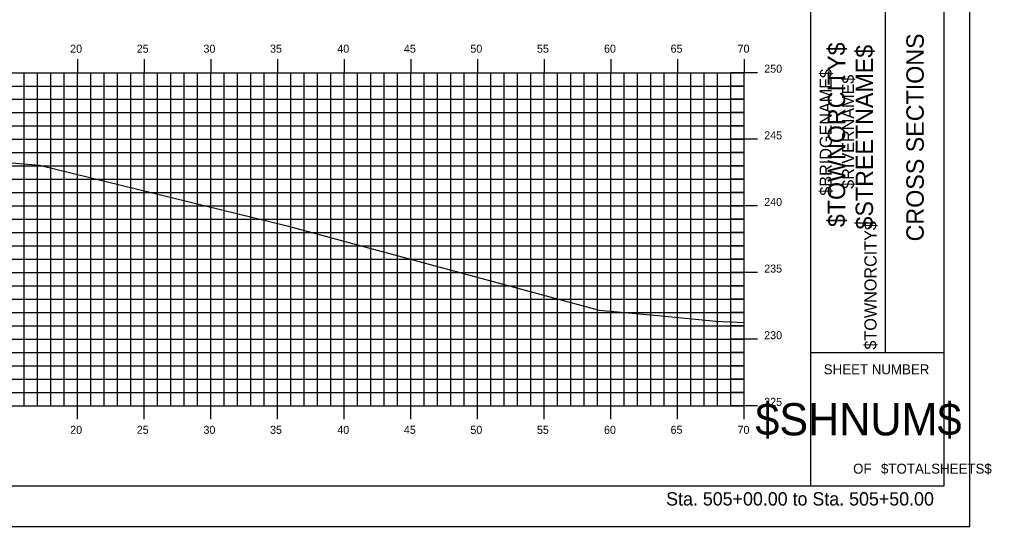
# Model space of a CAD drawing. Extents: x 1168600 to 1177589, y 610178 to 611246.
# Drawn here: x 1171529.1 to 1171602, y 610268.7 to 610306.8 of the extents above; entities that cross this region are included whole.
import ezdxf

# ---------------------------------------------------------------- set-up
doc = ezdxf.new("R2010")
doc.units = 0
for name, color, linetype in [('_Construction', 7, 'Continuous'), ('_Station Equation', 7, 'Continuous'), ('H_V ANNOTATION', 7, 'Continuous'), ('MAJOR', 7, 'Continuous'), ('MINOR', 7, 'Continuous')]:
    doc.layers.add(name, color=color, linetype=linetype)

msp = doc.modelspace()

# ---------------------------------------------------------------- linework, layer by layer
at = {"layer": '_Construction'}
for p, q in [((1171588.498, 610271.804), (1171588.498, 610376.804)), ((1171598.498, 610271.804), (1171598.498, 610376.804)), ((1171594.089, 610281.804), (1171594.089, 610316.804)), ((1171588.498, 610281.804), (1171598.498, 610281.804)), ((1171438.498, 610271.801), (1171598.498, 610271.801))]:
    msp.add_line(p, q, dxfattribs=at)
msp.add_lwpolyline([(1171430.404, 610268.742), (1171600.404, 610268.742), (1171600.404, 610378.742), (1171430.404, 610378.742)], close=True, dxfattribs=at)
at = {"layer": '_Station Equation'}
msp.add_lwpolyline([(1171527.644, 610296.11), (1171530.653, 610295.865), (1171549.218, 610291.31), (1171572.609, 610284.992), (1171577.284, 610284.55), (1171581.359, 610284.143), (1171583.497, 610284.062)], dxfattribs=at)
at = {"layer": 'MAJOR'}
for p, q in [((1171533.497, 610303.803), (1171533.497, 610302.801)), ((1171538.497, 610303.803), (1171538.497, 610302.801)), ((1171543.497, 610303.803), (1171543.497, 610302.801)), ((1171548.497, 610303.803), (1171548.497, 610302.801)), ((1171553.497, 610303.803), (1171553.497, 610302.801)), ((1171558.497, 610303.803), (1171558.497, 610302.801)), ((1171563.497, 610303.803), (1171563.497, 610302.801)), ((1171568.497, 610303.803), (1171568.497, 610302.801)), ((1171573.497, 610303.803), (1171573.497, 610302.801)), ((1171578.497, 610303.803), (1171578.497, 610302.801)), ((1171583.497, 610303.803), (1171583.497, 610302.801)), ((1171443.497, 610302.801), (1171583.497, 610302.801)), ((1171443.497, 610302.801), (1171583.497, 610302.801)), ((1171533.497, 610277.801), (1171533.497, 610302.801)), ((1171538.497, 610277.801), (1171538.497, 610302.801)), ((1171543.497, 610277.801), (1171543.497, 610302.801)), ((1171548.497, 610277.801), (1171548.497, 610302.801)), ((1171553.497, 610277.801), (1171553.497, 610302.801)), ((1171558.497, 610277.801), (1171558.497, 610302.801)), ((1171563.497, 610277.801), (1171563.497, 610302.801)), ((1171568.497, 610277.801), (1171568.497, 610302.801)), ((1171573.497, 610277.801), (1171573.497, 610302.801)), ((1171578.497, 610277.801), (1171578.497, 610302.801)), ((1171584.499, 610302.801), (1171582.495, 610302.801)), ((1171583.497, 610277.801), (1171583.497, 610302.801)), ((1171583.497, 610277.801), (1171583.497, 610302.801)), ((1171443.497, 610297.801), (1171583.497, 610297.801)), ((1171584.499, 610297.801), (1171582.495, 610297.801)), ((1171443.497, 610292.801), (1171583.497, 610292.801)), ((1171584.499, 610292.801), (1171582.495, 610292.801)), ((1171443.497, 610287.801), (1171583.497, 610287.801)), ((1171584.499, 610287.801), (1171582.495, 610287.801)), ((1171443.497, 610282.801), (1171583.497, 610282.801)), ((1171584.499, 610282.801), (1171582.495, 610282.801)), ((1171443.497, 610277.801), (1171583.497, 610277.801)), ((1171443.497, 610277.801), (1171583.497, 610277.801)), ((1171533.497, 610276.799), (1171533.497, 610277.801)), ((1171538.497, 610276.799), (1171538.497, 610277.801)), ((1171543.497, 610276.799), (1171543.497, 610277.801)), ((1171548.497, 610276.799), (1171548.497, 610277.801)), ((1171553.497, 610276.799), (1171553.497, 610277.801)), ((1171558.497, 610276.799), (1171558.497, 610277.801)), ((1171563.497, 610276.799), (1171563.497, 610277.801)), ((1171568.497, 610276.799), (1171568.497, 610277.801)), ((1171573.497, 610276.799), (1171573.497, 610277.801)), ((1171578.497, 610276.799), (1171578.497, 610277.801)), ((1171584.499, 610277.801), (1171582.495, 610277.801)), ((1171583.497, 610276.799), (1171583.497, 610277.801))]:
    msp.add_line(p, q, dxfattribs=at)
at = {"layer": 'MINOR'}
for p, q in [((1171529.497, 610277.801), (1171529.497, 610302.801)), ((1171530.497, 610277.801), (1171530.497, 610302.801)), ((1171531.497, 610277.801), (1171531.497, 610302.801)), ((1171532.497, 610277.801), (1171532.497, 610302.801)), ((1171534.497, 610277.801), (1171534.497, 610302.801)), ((1171535.497, 610277.801), (1171535.497, 610302.801)), ((1171536.497, 610277.801), (1171536.497, 610302.801)), ((1171537.497, 610277.801), (1171537.497, 610302.801)), ((1171539.497, 610277.801), (1171539.497, 610302.801)), ((1171540.497, 610277.801), (1171540.497, 610302.801)), ((1171541.497, 610277.801), (1171541.497, 610302.801)), ((1171542.497, 610277.801), (1171542.497, 610302.801)), ((1171544.497, 610277.801), (1171544.497, 610302.801)), ((1171545.497, 610277.801), (1171545.497, 610302.801)), ((1171546.497, 610277.801), (1171546.497, 610302.801)), ((1171547.497, 610277.801), (1171547.497, 610302.801)), ((1171549.497, 610277.801), (1171549.497, 610302.801)), ((1171550.497, 610277.801), (1171550.497, 610302.801)), ((1171551.497, 610277.801), (1171551.497, 610302.801)), ((1171552.497, 610277.801), (1171552.497, 610302.801)), ((1171554.497, 610277.801), (1171554.497, 610302.801)), ((1171555.497, 610277.801), (1171555.497, 610302.801)), ((1171556.497, 610277.801), (1171556.497, 610302.801)), ((1171557.497, 610277.801), (1171557.497, 610302.801)), ((1171559.497, 610277.801), (1171559.497, 610302.801)), ((1171560.497, 610277.801), (1171560.497, 610302.801)), ((1171561.497, 610277.801), (1171561.497, 610302.801)), ((1171562.497, 610277.801), (1171562.497, 610302.801)), ((1171564.497, 610277.801), (1171564.497, 610302.801)), ((1171565.497, 610277.801), (1171565.497, 610302.801)), ((1171566.497, 610277.801), (1171566.497, 610302.801)), ((1171567.497, 610277.801), (1171567.497, 610302.801)), ((1171569.497, 610277.801), (1171569.497, 610302.801)), ((1171570.497, 610277.801), (1171570.497, 610302.801)), ((1171571.497, 610277.801), (1171571.497, 610302.801)), ((1171572.497, 610277.801), (1171572.497, 610302.801)), ((1171574.497, 610277.801), (1171574.497, 610302.801)), ((1171575.497, 610277.801), (1171575.497, 610302.801)), ((1171576.497, 610277.801), (1171576.497, 610302.801)), ((1171577.497, 610277.801), (1171577.497, 610302.801)), ((1171579.497, 610277.801), (1171579.497, 610302.801)), ((1171580.497, 610277.801), (1171580.497, 610302.801)), ((1171581.497, 610277.801), (1171581.497, 610302.801)), ((1171582.497, 610277.801), (1171582.497, 610302.801)), ((1171443.497, 610301.801), (1171583.497, 610301.801)), ((1171583.497, 610301.801), (1171582.495, 610301.801)), ((1171443.497, 610300.801), (1171583.497, 610300.801)), ((1171583.497, 610300.801), (1171582.495, 610300.801)), ((1171443.497, 610299.801), (1171583.497, 610299.801)), ((1171583.497, 610299.801), (1171582.495, 610299.801)), ((1171443.497, 610298.801), (1171583.497, 610298.801)), ((1171583.497, 610298.801), (1171582.495, 610298.801)), ((1171443.497, 610296.801), (1171583.497, 610296.801)), ((1171583.497, 610296.801), (1171582.495, 610296.801)), ((1171443.497, 610295.801), (1171583.497, 610295.801)), ((1171583.497, 610295.801), (1171582.495, 610295.801)), ((1171443.497, 610294.801), (1171583.497, 610294.801)), ((1171583.497, 610294.801), (1171582.495, 610294.801)), ((1171443.497, 610293.801), (1171583.497, 610293.801)), ((1171583.497, 610293.801), (1171582.495, 610293.801)), ((1171443.497, 610291.801), (1171583.497, 610291.801)), ((1171583.497, 610291.801), (1171582.495, 610291.801)), ((1171443.497, 610290.801), (1171583.497, 610290.801)), ((1171583.497, 610290.801), (1171582.495, 610290.801)), ((1171443.497, 610289.801), (1171583.497, 610289.801)), ((1171583.497, 610289.801), (1171582.495, 610289.801)), ((1171443.497, 610288.801), (1171583.497, 610288.801)), ((1171583.497, 610288.801), (1171582.495, 610288.801)), ((1171443.497, 610286.801), (1171583.497, 610286.801)), ((1171583.497, 610286.801), (1171582.495, 610286.801)), ((1171443.497, 610285.801), (1171583.497, 610285.801)), ((1171583.497, 610285.801), (1171582.495, 610285.801)), ((1171443.497, 610284.801), (1171583.497, 610284.801)), ((1171583.497, 610284.801), (1171582.495, 610284.801)), ((1171443.497, 610283.801), (1171583.497, 610283.801)), ((1171583.497, 610283.801), (1171582.495, 610283.801)), ((1171443.497, 610281.801), (1171583.497, 610281.801)), ((1171583.497, 610281.801), (1171582.495, 610281.801)), ((1171443.497, 610280.801), (1171583.497, 610280.801)), ((1171583.497, 610280.801), (1171582.495, 610280.801)), ((1171443.497, 610279.801), (1171583.497, 610279.801)), ((1171583.497, 610279.801), (1171582.495, 610279.801)), ((1171443.497, 610278.801), (1171583.497, 610278.801)), ((1171583.497, 610278.801), (1171582.495, 610278.801))]:
    msp.add_line(p, q, dxfattribs=at)

# ---------------------------------------------------------------- texts
at = {"layer": '_Construction'}
for s, height, rotation, p in [('$TOWNORCITY$', 1.30428, 90, (1171591.07, 610291.212)), ('CROSS SECTIONS', 1.30428, 90, (1171596.962, 610290.143)), ('$STREETNAME$', 1.30428, 90, (1171593.157, 610291.032)), ('$BRIDGENAME$', 0.90716, 90, (1171590.064, 610293.572)), ('$RIVERNAME$', 0.90716, 90, (1171591.741, 610294.087)), ('$TOWNORCITY$', 0.90716, 90, (1171593.418, 610282.025)), ('SHEET NUMBER', 0.74527, 360, (1171589.463, 610280.168)), ('$SHNUM$', 2.4194, 360, (1171584.331, 610275.584)), ('OF', 0.7453, 360, (1171591.665, 610272.714)), ('$TOTALSHEETS$', 0.74527, 360, (1171593.754, 610272.714))]:
    msp.add_text(s, height=height, rotation=rotation, dxfattribs=at).set_placement(p)
at = {"layer": 'H_V ANNOTATION'}
for s, height, p in [('20', 0.6, (1171532.951, 610304.301)), ('25', 0.6, (1171537.943, 610304.301)), ('30', 0.6, (1171542.946, 610304.301)), ('35', 0.6, (1171547.938, 610304.301)), ('40', 0.6, (1171552.984, 610304.301)), ('45', 0.6, (1171557.976, 610304.301)), ('50', 0.6, (1171562.962, 610304.301)), ('55', 0.6, (1171567.954, 610304.301)), ('60', 0.6, (1171572.984, 610304.301)), ('65', 0.6, (1171577.976, 610304.301)), ('70', 0.6, (1171582.999, 610304.301)), ('250', 0.6, (1171584.997, 610302.801)), ('245', 0.6, (1171584.997, 610297.801)), ('240', 0.6, (1171584.997, 610292.801)), ('235', 0.6, (1171584.997, 610287.801)), ('230', 0.6, (1171584.997, 610282.801)), ('225', 0.6, (1171584.997, 610277.801)), ('20', 0.6, (1171532.951, 610275.701)), ('25', 0.6, (1171537.943, 610275.701)), ('30', 0.6, (1171542.946, 610275.701)), ('35', 0.6, (1171547.938, 610275.701)), ('40', 0.6, (1171552.984, 610275.701)), ('45', 0.6, (1171557.976, 610275.701)), ('50', 0.6, (1171562.962, 610275.701)), ('55', 0.6, (1171567.954, 610275.701)), ('60', 0.6, (1171572.984, 610275.701)), ('65', 0.6, (1171577.976, 610275.701)), ('70', 0.6, (1171582.999, 610275.701)), ('Sta. 505+00.00 to Sta. 505+50.00', 1.0002, (1171577.643, 610270.321))]:
    msp.add_text(s, height=height, dxfattribs=at).set_placement(p)

doc.saveas('drawing.dxf')
